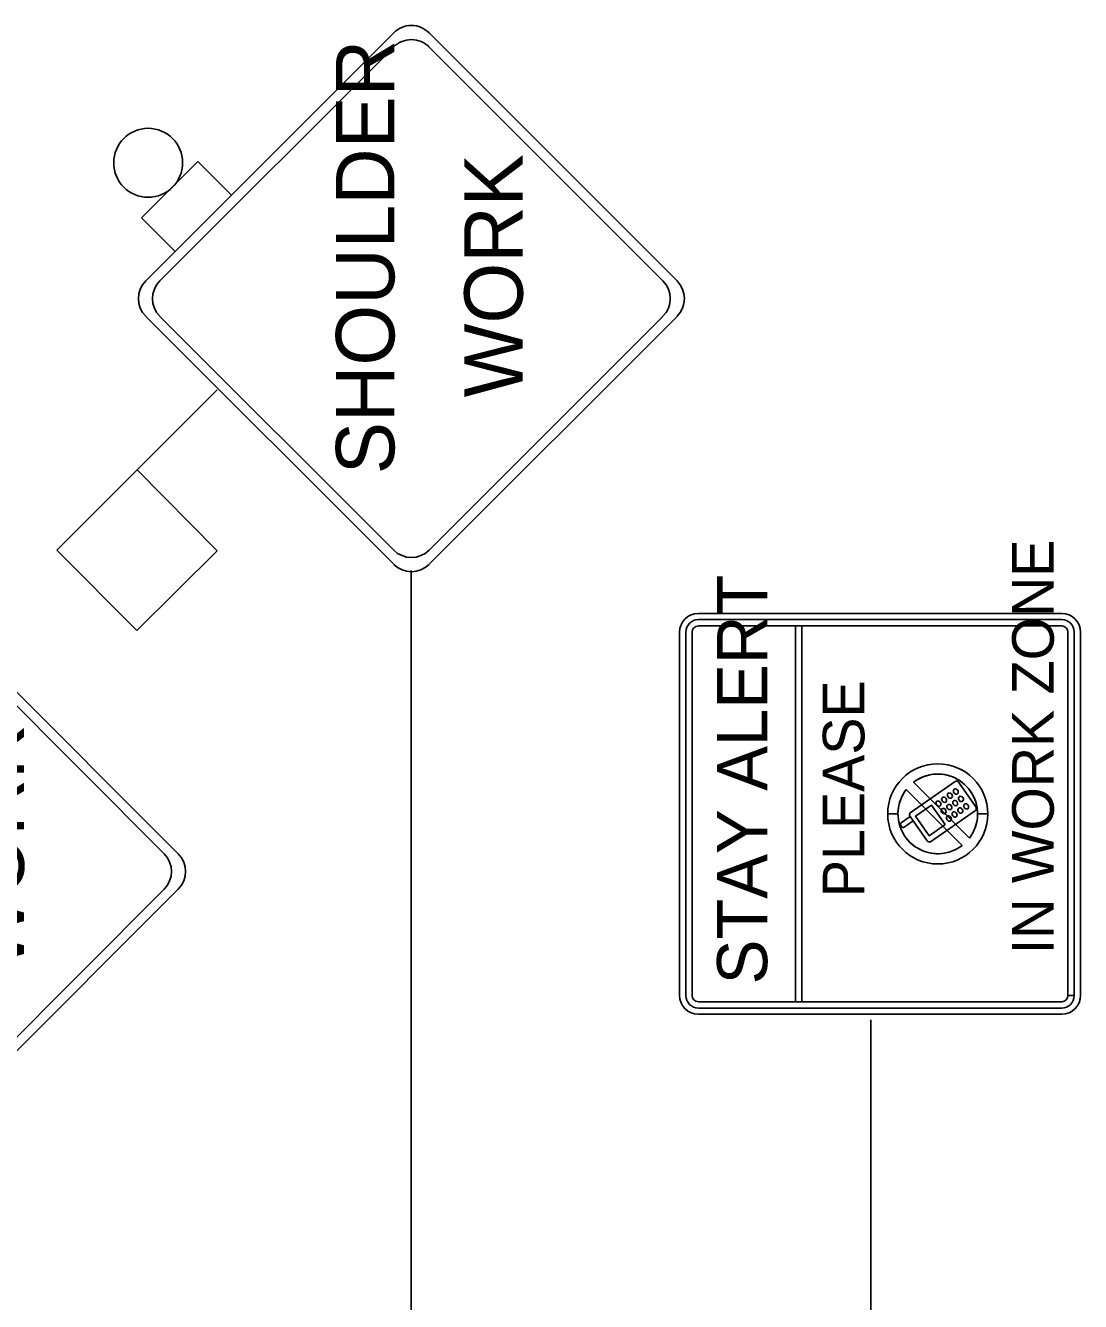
# Model space of a CAD drawing. Extents: x 2155255 to 2162649, y 140388 to 141878.
# Drawn here: x 2156712.5 to 2156838.8, y 141287.5 to 141440.3 of the extents above; entities that cross this region are included whole.
import ezdxf

# ---------------------------------------------------------------- set-up
doc = ezdxf.new("R2010")
doc.units = 0
for name, color, linetype in [('5', 7, 'Continuous'), ('Default', 7, 'Continuous'), ('PR_Dimensions1', 7, 'Continuous'), ('PR_Traffic_Control_Devices_Temp', 7, 'Continuous')]:
    doc.layers.add(name, color=color, linetype=linetype)

# ---------------------------------------------------------------- blocks, each defined once
blk = doc.blocks.new('FLSHFLAG')
at = {"layer": 'Default'}
for p, q in [((-1.202, 14.125), (0.838, 16.147)), ((0.838, 16.147), (4.9, 12.085)), ((0.819, 12.085), (-1.202, 14.125)), ((0.819, 12.085), (2.86, 14.106)), ((9.258, 14.004), (8.403, 13.149)), ((9.258, 14.004), (10.685, 12.576)), ((10.685, 12.576), (9.831, 11.722))]:
    blk.add_line(p, q, dxfattribs=at)
blk.add_circle((10.653, 13.836), 0.873, dxfattribs=at)
blk = doc.blocks.new('CW21-5')
at = {"layer": '5'}
for p, q in [((0.318, 3.005), (2.651, 5.339)), ((5.338, 3.005), (3.005, 5.339)), ((2.651, 0.318), (0.318, 2.652)), ((3.005, 0.318), (5.338, 2.652))]:
    blk.add_line(p, q, dxfattribs=at)
for centre, start, end in [((2.828, 5.162), 45, 135), ((0.495, 2.828), 135, 225), ((5.162, 2.828), 315, 45), ((2.828, 0.495), 225, 315)]:
    blk.add_arc(centre, 0.25, start, end, dxfattribs=at)
at = {"layer": 'Default'}
for p, q in [((0.177, 3.005), (2.651, 5.48)), ((5.48, 3.005), (3.005, 5.48)), ((2.651, 0.177), (0.177, 2.652)), ((3.005, 0.177), (5.48, 2.652))]:
    blk.add_line(p, q, dxfattribs=at)
for centre, start, end in [((2.828, 5.303), 45, 135), ((0.353, 2.828), 135, 225), ((5.303, 2.828), 315, 45), ((2.828, 0.354), 225, 315)]:
    blk.add_arc(centre, 0.25, start, end, dxfattribs=at)
for s, p in [('SHOULDER', (1.076, 2.998)), ('WORK', (1.843, 1.717))]:
    blk.add_text(s, height=0.5833, dxfattribs=at).set_placement(p)

msp = doc.modelspace()

# ---------------------------------------------------------------- linework, layer by layer
at = {"layer": 'PR_Dimensions1'}
for p, q in [((2156758.68, 141198.84), (2156758.68, 141375.07)), ((2156813.73, 141199.25), (2156813.73, 141321.26))]:
    msp.add_line(p, q, dxfattribs=at)
at = {"layer": 'PR_Traffic_Control_Devices_Temp'}
for p, q in [((2156823.83, 141349.81), (2156818.46, 141346.06)), ((2156823.83, 141349.81), (2156818.46, 141346.06)), ((2156826.29, 141346.79), (2156824.26, 141349.69)), ((2156826.29, 141346.79), (2156824.26, 141349.69)), ((2156819.08, 141345.65), (2156820.98, 141346.98)), ((2156820.98, 141346.98), (2156822.62, 141344.64)), ((2156818.43, 141345.62), (2156817.37, 141344.87)), ((2156818.43, 141345.61), (2156818.43, 141345.62)), ((2156818.43, 141345.61), (2156818.8, 141345.08)), ((2156818.43, 141345.61), (2156818.8, 141345.08)), ((2156818.8, 141345.08), (2156818.43, 141345.61)), ((2156818.43, 141345.61), (2156818.43, 141345.61)), ((2156820.72, 141343.31), (2156819.08, 141345.65)), ((2156820.89, 141342.59), (2156826.26, 141346.35)), ((2156820.89, 141342.59), (2156826.26, 141346.35)), ((2156817.34, 141344.54), (2156817.42, 141344.43)), ((2156817.74, 141344.34), (2156818.8, 141345.08)), ((2156818.8, 141345.08), (2156820.46, 141342.72)), ((2156818.8, 141345.08), (2156820.46, 141342.72)), ((2156822.62, 141344.64), (2156820.72, 141343.31))]:
    msp.add_line(p, q, dxfattribs=at)
for points in [[(2156836.59, 141369.94), (2156805.08, 141369.94), (2156793.08, 141369.94)], [(2156836.59, 141369.19), (2156793.08, 141369.19)], [(2156793.08, 141368.44), (2156836.59, 141368.44)], [(2156790.83, 141367.69), (2156790.83, 141324.18)], [(2156791.58, 141367.69), (2156791.58, 141324.18)], [(2156792.33, 141324.18), (2156792.33, 141367.69)], [(2156837.34, 141367.69), (2156837.34, 141324.19), (2156838.09, 141324.19)], [(2156838.09, 141324.19), (2156838.09, 141367.69)], [(2156838.84, 141324.18), (2156838.84, 141367.69)], [(2156824.66, 141342.16), (2156817.97, 141348.84)], [(2156824.66, 141342.15), (2156817.97, 141348.84)], [(2156825.53, 141343.02), (2156818.84, 141349.71)], [(2156818.84, 141349.71), (2156825.53, 141343.03)], [(2156826.29, 141346.79), (2156824.26, 141349.69)], [(2156822.62, 141344.64), (2156820.72, 141343.31), (2156819.08, 141345.65), (2156820.98, 141346.98), (2156822.62, 141344.64)], [(2156815.75, 141345.93), (2156816.98, 141345.93)], [(2156816.98, 141345.93), (2156815.75, 141345.93)], [(2156827.75, 141345.93), (2156826.52, 141345.93)], [(2156826.52, 141345.93), (2156827.75, 141345.93)], [(2156817.34, 141344.54), (2156817.42, 141344.43)], [(2156838.09, 141324.18), (2156837.34, 141324.18)], [(2156836.59, 141323.43), (2156793.08, 141323.43)], [(2156793.08, 141322.68), (2156836.59, 141322.68)], [(2156793.08, 141321.93), (2156805.08, 141321.93), (2156836.59, 141321.93)]]:
    msp.add_lwpolyline(points, dxfattribs=at)
for points in [[(2156804.7, 141323.43), (2156805.45, 141323.43), (2156805.45, 141368.44), (2156804.7, 141368.44)], [(2156804.7, 141323.43), (2156805.45, 141323.43), (2156805.45, 141368.44), (2156804.7, 141368.44)], [(2156822.62, 141344.64), (2156820.98, 141346.98), (2156819.08, 141345.65), (2156820.72, 141343.31)], [(2156818.8, 141345.08), (2156817.74, 141344.34), (2156818.8, 141345.08), (2156818.43, 141345.62), (2156817.37, 141344.87), (2156818.43, 141345.62), (2156818.43, 141345.61), (2156818.43, 141345.61), (2156820.46, 141342.72), (2156820.46, 141342.72)]]:
    msp.add_lwpolyline(points, close=True, dxfattribs=at)
msp.add_circle((2156821.75, 141345.93), 6, dxfattribs=at)
msp.add_circle((2156821.75, 141345.93), 6, dxfattribs=at)
for centre, radius, start, end in [((2156793.08, 141367.69), 2.25, 90, 180), ((2156836.59, 141367.69), 2.25, 360, 90), ((2156793.08, 141367.69), 1.5, 90, 180), ((2156793.08, 141367.69), 0.75, 90, 180), ((2156836.59, 141367.69), 1.5, 360, 90), ((2156836.59, 141367.69), 0.75, 360, 90), ((2156821.75, 141345.93), 6, 359.9992, 179.9992), ((2156821.75, 141345.93), 4.77, 322.4137, 127.5863), ((2156821.75, 141345.93), 4.77, 322.4137, 127.5863), ((2156821.75, 141345.93), 4.77, 359.9991, 127.5866), ((2156821.75, 141345.93), 4.77, 142.4137, 307.5863), ((2156821.75, 141345.93), 4.77, 142.4137, 307.5863), ((2156821.75, 141345.93), 4.77, 142.4162, 180.0037), ((2156821.75, 141345.93), 6, 180.0031, 359.9938), ((2156821.75, 141345.93), 4.77, 180.004, 307.5856), ((2156821.75, 141345.93), 4.77, 322.4117, 359.9933), ((2156793.08, 141324.18), 2.25, 180, 270), ((2156793.08, 141324.18), 1.5, 180, 270), ((2156793.08, 141324.18), 0.75, 180, 270), ((2156836.59, 141324.18), 2.25, 270, 0), ((2156836.59, 141324.18), 1.5, 270, 0), ((2156836.59, 141324.18), 0.75, 270, 360)]:
    msp.add_arc(centre, radius, start, end, dxfattribs=at)
for centre, major_axis in [((2156823.91, 141348.61), (0.196, -0.28)), ((2156823.91, 141348.61), (0.196, -0.28)), ((2156823.91, 141348.61), (0.196, -0.28)), ((2156821.83, 141347.16), (0.196, -0.28)), ((2156821.83, 141347.16), (0.196, -0.28)), ((2156821.83, 141347.16), (0.196, -0.28)), ((2156822.51, 141347.63), (0.196, -0.28)), ((2156822.51, 141347.63), (0.196, -0.28)), ((2156822.51, 141347.63), (0.196, -0.28)), ((2156823.13, 141346.75), (-0.196, 0.28)), ((2156823.13, 141346.75), (-0.196, 0.28)), ((2156823.13, 141346.75), (-0.196, 0.28)), ((2156823.2, 141348.12), (0.196, -0.28)), ((2156823.2, 141348.12), (0.196, -0.28)), ((2156823.2, 141348.12), (0.196, -0.28)), ((2156823.83, 141347.23), (-0.196, 0.28)), ((2156823.83, 141347.23), (-0.196, 0.28)), ((2156823.83, 141347.23), (-0.196, 0.28)), ((2156824.53, 141347.72), (-0.196, 0.28)), ((2156824.53, 141347.72), (-0.196, 0.28)), ((2156824.53, 141347.72), (-0.196, 0.28)), ((2156825.15, 141346.83), (-0.196, 0.28)), ((2156825.15, 141346.83), (-0.196, 0.28)), ((2156825.15, 141346.83), (-0.196, 0.28)), ((2156822.45, 141346.27), (-0.196, 0.28)), ((2156822.45, 141346.27), (-0.196, 0.28)), ((2156822.45, 141346.27), (-0.196, 0.28)), ((2156823.08, 141345.38), (-0.196, 0.28)), ((2156823.08, 141345.38), (-0.196, 0.28)), ((2156823.08, 141345.38), (-0.196, 0.28)), ((2156823.76, 141345.86), (-0.196, 0.28)), ((2156823.76, 141345.86), (-0.196, 0.28)), ((2156823.76, 141345.86), (-0.196, 0.28)), ((2156824.45, 141346.34), (-0.196, 0.28)), ((2156824.45, 141346.34), (-0.196, 0.28))]:
    msp.add_ellipse(centre, major_axis=major_axis, ratio=0.8, dxfattribs=at)
for centre, major_axis, start_param, end_param in [((2156824.03, 141349.53), (-0.2, 0.285), 4.712389, 6.283185), ((2156824.03, 141349.53), (-0.2, 0.285), 4.712389, 6.283185), ((2156824.03, 141349.53), (-0.2, 0.285), 4.712389, 6.283185), ((2156818.66, 141345.77), (-0.2, 0.285), 0, 1.570796), ((2156818.66, 141345.77), (0.2, -0.285), 3.141593, 4.712389), ((2156818.66, 141345.77), (0.2, -0.285), 3.141593, 4.712389), ((2156818.66, 141345.77), (-0.2, 0.285), 0, 1.570795), ((2156826.06, 141346.63), (0.2, -0.285), 0, 1.570796), ((2156826.06, 141346.63), (0.2, -0.285), 6.283185, 7.853982), ((2156826.06, 141346.63), (0.2, -0.285), 0, 1.570796), ((2156817.52, 141344.66), (-0.15, 0.214), 0, 1.570796), ((2156817.52, 141344.66), (0.15, -0.214), 3.141593, 4.712389), ((2156817.52, 141344.66), (-0.15, 0.214), 0, 1.570796), ((2156817.59, 141344.55), (0.15, -0.214), 4.712389, 6.283185), ((2156817.59, 141344.55), (0.15, -0.214), 4.712389, 6.283185), ((2156817.59, 141344.55), (0.15, -0.214), 4.712389, 6.283185), ((2156820.69, 141342.88), (0.2, -0.285), 4.712389, 6.283185), ((2156820.69, 141342.88), (0.2, -0.285), 4.712389, 6.283185), ((2156820.69, 141342.88), (0.2, -0.285), 4.712389, 6.283185), ((2156820.69, 141342.88), (0.2, -0.285), 4.712389, 6.283185)]:
    msp.add_ellipse(centre, major_axis=major_axis, ratio=0.8, start_param=start_param, end_param=end_param, dxfattribs=at)

# ---------------------------------------------------------------- block references
at = {"layer": 'PR_Traffic_Control_Devices_Temp', "rotation": 90}
for name, p, xscale, yscale in [('CW21-5', (2156792.65, 141373.69), 12, 12), ('FLSHFLAG', (2156792.55, 141373.56), 4.7244, 4.7244), ('CW21-5', (2156732.92, 141305.1), 12, 12)]:
    msp.add_blockref(name, p, dxfattribs=dict(at, xscale=xscale, yscale=yscale))

# ---------------------------------------------------------------- texts
at = {"layer": 'PR_Traffic_Control_Devices_Temp'}
for s, height, p in [('IN WORK ZONE', 4.9872, (2156835.64, 141329.12)), ('STAY ALERT', 6, (2156801.32, 141325.52)), ('PLEASE', 4.987, (2156812.96, 141335.96))]:
    msp.add_text(s, height=height, rotation=90, dxfattribs=at).set_placement(p)

doc.saveas('drawing.dxf')
